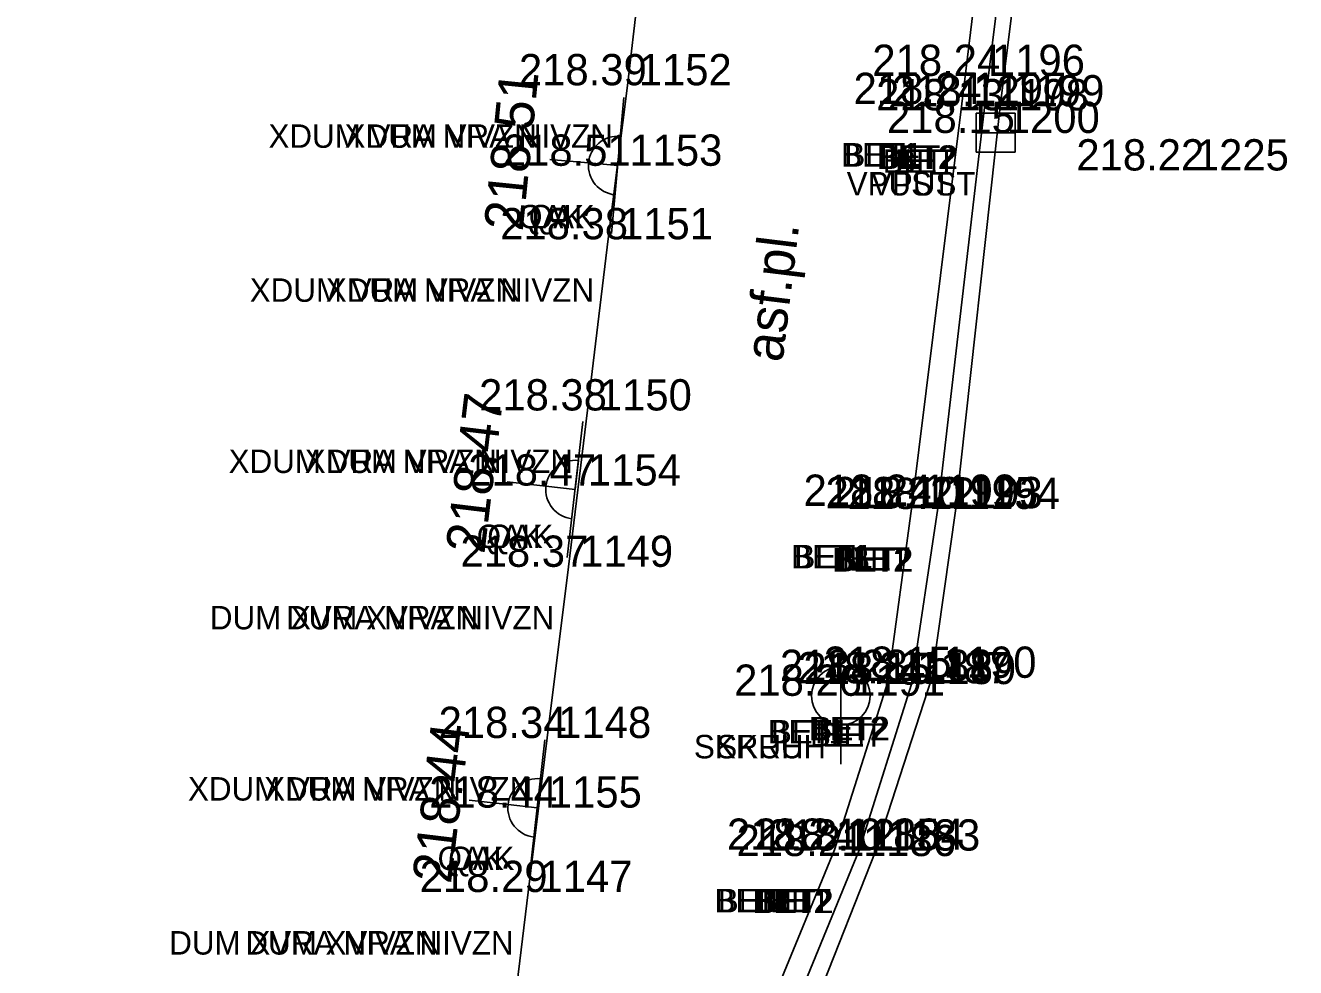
# Model space of a CAD drawing. Extents: x -471047 to -470889, y -1102859 to -1102000.
# Drawn here: x -470984.24 to -470967.99, y -1102458.3 to -1102446.24 of the extents above; entities that cross this region are included whole.
import ezdxf

# ---------------------------------------------------------------- set-up
doc = ezdxf.new("R2010")
doc.units = 0
for name, color, linetype in [('Vrstva 1', 7, 'Continuous'), ('Vrstva 10', 7, 'Continuous'), ('Vrstva 13', 7, 'Continuous'), ('Vrstva 22', 7, 'Continuous'), ('Vrstva 25', 7, 'Continuous'), ('Vrstva 28', 7, 'Continuous'), ('Vrstva 34', 7, 'Continuous'), ('Vrstva 35', 7, 'Continuous'), ('Vrstva 36', 7, 'Continuous'), ('Vrstva 38', 7, 'Continuous'), ('Vrstva 5', 7, 'Continuous'), ('Vrstva 7', 7, 'Continuous'), ('Vrstva 8', 7, 'Continuous')]:
    doc.layers.add(name, color=color, linetype=linetype)

msp = doc.modelspace()

# ---------------------------------------------------------------- linework, layer by layer
at = {"layer": 'Vrstva 1'}
for points in [[(-471040.344, -1102858.385), (-471031.676, -1102846.187), (-471026.357, -1102838.629), (-471023.212, -1102833.975), (-471019.21, -1102827.465), (-471016.861, -1102823.272), (-471013.099, -1102815.912), (-471010.824, -1102810.955), (-471007.329, -1102802.292), (-471005.34, -1102796.515), (-471002.842, -1102787.838), (-471001.3, -1102780.997), (-471000.19, -1102774.713), (-470999.247, -1102768.204), (-470998.794, -1102764.784), (-470997.199, -1102751.812), (-470994.899, -1102732.807), (-470992.551, -1102713.262), (-470990.326, -1102694.887), (-470988.122, -1102676.57), (-470985.812, -1102657.305), (-470983.537, -1102638.407), (-470981.386, -1102620.622), (-470979.843, -1102608.014), (-470976.377, -1102579.253), (-470972.945, -1102550.69), (-470970.475, -1102530.206), (-470967.905, -1102508.801), (-470965.053, -1102485.131), (-470962.734, -1102465.9), (-470960.173, -1102444.812), (-470957.795, -1102425.103), (-470954.965, -1102401.839), (-470953.834, -1102392.574), (-470952.33, -1102379.985), (-470950.744, -1102366.853), (-470948.978, -1102352.106), (-470947.037, -1102335.844), (-470944.949, -1102318.462), (-470944.013, -1102310.745), (-470942.39, -1102297.267), (-470939.519, -1102273.45), (-470937.593, -1102257.43), (-470936.064, -1102244.81), (-470934.114, -1102228.634), (-470931.621, -1102207.856), (-470929.536, -1102190.857), (-470926.572, -1102166.31), (-470924.91, -1102152.663), (-470923.413, -1102140.333), (-470921.923, -1102127.669), (-470921.155, -1102120.084), (-470920.446, -1102109.574), (-470919.912, -1102099.137), (-470919.63, -1102088.981), (-470919.523, -1102081.193), (-470919.563, -1102070.395), (-470919.714, -1102064.236), (-470920.134, -1102054.704), (-470920.462, -1102047.615), (-470920.599, -1102044.52), (-470920.743, -1102041.873), (-470921.125, -1102034.455), (-470921.774, -1102030.337), (-470922.418, -1102027.787), (-470923.734, -1102023.93), (-470924.872, -1102021.434), (-470926.752, -1102018.182), (-470927.953, -1102016.45), (-470929.616, -1102014.424), (-470932.252, -1102011.756), (-470935.111, -1102009.425), (-470938.391, -1102007.371), (-470942.651, -1102005.401)], [(-471041.328, -1102857.18), (-471032.144, -1102844.242), (-471027.583, -1102837.763), (-471024.388, -1102833.028), (-471020.451, -1102826.6), (-471018.089, -1102822.378), (-471014.542, -1102815.445), (-471012.233, -1102810.418), (-471009.247, -1102803.108), (-471006.795, -1102796.098), (-471004.315, -1102787.532), (-471002.782, -1102780.723), (-471001.674, -1102774.458), (-471000.75, -1102768.095), (-471000.28, -1102764.601), (-470998.692, -1102751.741), (-470996.378, -1102732.635), (-470994.028, -1102713.058), (-470991.808, -1102694.749), (-470989.616, -1102676.447), (-470987.284, -1102657.013), (-470985.031, -1102638.272), (-470982.87, -1102620.431), (-470981.334, -1102607.933), (-470977.881, -1102579.263), (-470974.429, -1102550.492), (-470971.964, -1102530.054), (-470969.391, -1102508.607), (-470966.54, -1102484.984), (-470964.231, -1102465.853), (-470961.679, -1102444.752), (-470959.304, -1102425.078), (-470956.455, -1102401.634), (-470955.339, -1102392.489), (-470953.812, -1102379.71), (-470952.249, -1102366.808), (-470950.479, -1102352.023), (-470948.536, -1102335.868), (-470946.426, -1102318.233), (-470945.493, -1102310.531), (-470943.864, -1102297.013), (-470940.984, -1102273.071), (-470939.078, -1102257.195), (-470937.559, -1102244.684), (-470935.592, -1102228.353), (-470933.101, -1102207.653), (-470931.011, -1102190.57), (-470928.046, -1102166.021), (-470926.409, -1102152.578), (-470924.898, -1102140.121), (-470923.427, -1102127.544), (-470922.647, -1102119.826), (-470921.919, -1102109.229), (-470921.42, -1102099.134), (-470921.127, -1102089.016), (-470921.023, -1102081.453), (-470921.061, -1102070.468), (-470921.209, -1102064.314), (-470921.666, -1102053.966), (-470922.156, -1102043.345), (-470922.299, -1102039.934), (-470922.637, -1102034.36), (-470923.091, -1102031.241), (-470923.847, -1102028.247), (-470925.083, -1102024.594), (-470926.222, -1102022.086), (-470928.04, -1102018.943), (-470929.138, -1102017.357), (-470930.929, -1102015.175), (-470933.062, -1102013.049), (-470936.379, -1102010.368), (-470939.169, -1102008.662), (-470942.899, -1102006.906), (-470945.661, -1102005.908)], [(-471043.557, -1102855.955), (-471035.129, -1102844.026), (-471029.872, -1102836.499), (-471026.577, -1102831.578), (-471022.675, -1102825.415), (-471020.123, -1102821.053), (-471016.667, -1102814.59), (-471014.208, -1102809.45), (-471011.177, -1102802.451), (-471008.55, -1102795.333), (-471006.082, -1102787.209), (-471004.464, -1102780.376), (-471003.265, -1102774.167), (-471002.327, -1102767.948), (-471001.636, -1102762.527), (-471000.297, -1102751.605), (-470997.959, -1102732.524), (-470995.602, -1102712.802), (-470993.412, -1102694.623), (-470991.21, -1102676.17), (-470988.891, -1102656.857), (-470986.625, -1102638.083), (-470984.455, -1102620.195), (-470982.936, -1102607.733), (-470979.497, -1102579.223), (-470976.023, -1102550.279), (-470973.554, -1102529.822), (-470970.991, -1102508.497), (-470968.146, -1102484.787), (-470965.835, -1102465.72), (-470963.284, -1102444.529), (-470960.91, -1102424.942), (-470958.043, -1102401.343), (-470956.946, -1102392.356), (-470955.396, -1102379.408), (-470953.851, -1102366.636), (-470952.049, -1102351.733), (-470950.124, -1102335.611), (-470948.034, -1102318.083), (-470947.094, -1102310.328), (-470945.421, -1102296.51), (-470942.58, -1102272.848), (-470940.675, -1102256.948), (-470939.176, -1102244.526), (-470937.187, -1102228.174), (-470934.708, -1102207.467), (-470932.621, -1102190.433), (-470929.634, -1102165.778), (-470928.004, -1102152.415), (-470926.45, -1102139.595), (-470925.003, -1102127.418), (-470924.249, -1102119.695), (-470923.515, -1102109.093), (-470923.018, -1102099.069), (-470922.711, -1102088.911), (-470922.643, -1102081.356), (-470922.797, -1102070.414), (-470923.018, -1102064.454), (-470923.52, -1102053.203), (-470923.823, -1102047.529), (-470924.123, -1102041.506), (-470924.462, -1102037.486), (-470924.934, -1102031.904), (-470925.664, -1102028.672), (-470926.771, -1102025.506), (-470927.959, -1102022.914), (-470929.674, -1102020.028), (-470930.76, -1102018.498), (-470932.447, -1102016.478), (-470935.215, -1102013.816), (-470937.644, -1102011.98), (-470940.381, -1102010.371), (-470943.968, -1102008.669), (-470947.145, -1102007.524), (-470950.874, -1102006.74)], [(-471044.756, -1102855.056), (-471036.376, -1102843.177), (-471031.167, -1102835.741), (-471027.859, -1102830.8), (-471023.934, -1102824.593), (-471021.43, -1102820.312), (-471018.011, -1102813.91), (-471015.536, -1102808.75), (-471012.578, -1102801.897), (-471009.95, -1102794.77), (-471007.561, -1102786.914), (-471005.936, -1102780.074), (-471004.727, -1102773.818), (-471003.828, -1102767.827), (-471003.121, -1102762.345), (-471001.787, -1102751.467), (-470999.446, -1102732.348), (-470997.073, -1102712.539), (-470994.902, -1102694.521), (-470992.696, -1102676.023), (-470990.376, -1102656.68), (-470988.131, -1102638.071), (-470985.947, -1102620.018), (-470984.417, -1102607.512), (-470980.993, -1102579.08), (-470977.514, -1102550.137), (-470975.048, -1102529.649), (-470972.488, -1102508.37), (-470969.618, -1102484.508), (-470967.34, -1102465.669), (-470964.767, -1102444.39), (-470962.402, -1102424.781), (-470959.534, -1102401.193), (-470958.432, -1102392.151), (-470956.883, -1102379.208), (-470955.335, -1102366.424), (-470953.535, -1102351.506), (-470951.606, -1102335.399), (-470949.519, -1102317.94), (-470948.575, -1102310.159), (-470946.889, -1102296.144), (-470944.056, -1102272.618), (-470942.139, -1102256.659), (-470940.657, -1102244.341), (-470938.638, -1102227.749), (-470936.19, -1102207.298), (-470934.102, -1102190.255), (-470931.124, -1102165.639), (-470929.492, -1102152.254), (-470927.915, -1102139.252), (-470926.46, -1102127.103), (-470925.74, -1102119.604), (-470925.012, -1102108.913), (-470924.523, -1102099.054), (-470924.217, -1102088.866), (-470924.148, -1102081.334), (-470924.301, -1102070.391), (-470924.518, -1102064.43), (-470924.97, -1102054.435), (-470925.588, -1102041.569), (-470925.963, -1102035.313), (-470926.405, -1102032.225), (-470927.078, -1102029.198), (-470928.123, -1102026.148), (-470929.318, -1102023.558), (-470930.84, -1102020.97), (-470931.868, -1102019.515), (-470933.443, -1102017.605), (-470936.26, -1102014.885), (-470938.429, -1102013.255), (-470941.213, -1102011.639), (-470944.847, -1102009.927), (-470947.723, -1102008.912), (-470951.444, -1102008.161), (-470954.511, -1102007.931), (-470957.895, -1102008.041)]]:
    msp.add_spline(points, degree=3, dxfattribs=at)
at = {"layer": 'Vrstva 10'}
for p, q in [((-470976.537, -1102447.015), (-470975.875, -1102441.337)), ((-470977.049, -1102451.166), (-470976.783, -1102448.976)), ((-470977.565, -1102455.356), (-470977.291, -1102453.17)), ((-470978.077, -1102459.537), (-470977.807, -1102457.33))]:
    msp.add_line(p, q, dxfattribs=at)
at = {"layer": 'Vrstva 13'}
for p, q in [((-470976.738, -1102448.908), (-470976.582, -1102447.166)), ((-470976.66, -1102448.037), (-470976.626, -1102447.664)), ((-470977.033, -1102448.003), (-470977.531, -1102447.959)), ((-470977.033, -1102448.003), (-470976.66, -1102448.037)), ((-470977.009, -1102448.006), (-470977.009, -1102448.006)), ((-470977.305, -1102453.051), (-470977.107, -1102451.313)), ((-470977.206, -1102452.182), (-470977.163, -1102451.809)), ((-470977.578, -1102452.14), (-470978.075, -1102452.083)), ((-470977.578, -1102452.14), (-470977.206, -1102452.182)), ((-470977.554, -1102452.142), (-470977.554, -1102452.142)), ((-470977.791, -1102457.123), (-470977.591, -1102455.385)), ((-470977.691, -1102456.254), (-470977.648, -1102455.881)), ((-470978.064, -1102456.211), (-470978.56, -1102456.154)), ((-470978.064, -1102456.211), (-470977.691, -1102456.254)), ((-470978.039, -1102456.214), (-470978.039, -1102456.214))]:
    msp.add_line(p, q, dxfattribs=at)
for centre, start, end in [((-470976.66, -1102448.037), 84.8548, 174.8548), ((-470976.66, -1102448.037), 174.8548, 264.8548), ((-470977.206, -1102452.182), 83.5126, 173.5126), ((-470977.206, -1102452.182), 173.5126, 263.5126), ((-470977.691, -1102456.254), 83.4375, 173.4375), ((-470977.691, -1102456.254), 173.4375, 263.4375)]:
    msp.add_arc(centre, 0.375, start, end, dxfattribs=at)
at = {"layer": 'Vrstva 25'}
for p, q in [((-470972.075, -1102447.367), (-470972.075, -1102447.867)), ((-470971.575, -1102447.367), (-470972.075, -1102447.367)), ((-470971.575, -1102447.867), (-470971.575, -1102447.367)), ((-470972.075, -1102447.617), (-470971.575, -1102447.617)), ((-470972.075, -1102447.867), (-470971.575, -1102447.867)), ((-470973.806, -1102455.195), (-470973.806, -1102454.445)), ((-470973.806, -1102455.195), (-470973.806, -1102455.695))]:
    msp.add_line(p, q, dxfattribs=at)
msp.add_circle((-470973.806, -1102454.82), 0.375, dxfattribs=at)
at = {"layer": 'Vrstva 28'}
for p, q in [((-470976.783, -1102448.976), (-470976.537, -1102447.015)), ((-470977.291, -1102453.17), (-470977.049, -1102451.166)), ((-470977.807, -1102457.33), (-470977.565, -1102455.356))]:
    msp.add_line(p, q, dxfattribs=at)
at = {"layer": 'Vrstva 34'}
for p, q in [((-470972.02, -1102446.89), (-470972.02, -1102446.89)), ((-470976.54, -1102447.01), (-470976.54, -1102447.01)), ((-470972.26, -1102447.25), (-470972.26, -1102447.25)), ((-470971.97, -1102447.33), (-470971.97, -1102447.33)), ((-470971.77, -1102447.28), (-470971.77, -1102447.28)), ((-470971.83, -1102447.62), (-470971.83, -1102447.62)), ((-470976.66, -1102448.04), (-470976.66, -1102448.04)), ((-470969.41, -1102448.1), (-470969.41, -1102448.1)), ((-470976.78, -1102448.98), (-470976.78, -1102448.98)), ((-470977.05, -1102451.17), (-470977.05, -1102451.17)), ((-470977.19, -1102452.13), (-470977.19, -1102452.13)), ((-470972.9, -1102452.39), (-470972.9, -1102452.39)), ((-470972.62, -1102452.42), (-470972.62, -1102452.42)), ((-470972.56, -1102452.42), (-470972.56, -1102452.42)), ((-470972.34, -1102452.43), (-470972.34, -1102452.43)), ((-470977.29, -1102453.17), (-470977.29, -1102453.17)), ((-470973.2, -1102454.63), (-470973.2, -1102454.63)), ((-470972.98, -1102454.66), (-470972.98, -1102454.66)), ((-470972.9, -1102454.67), (-470972.9, -1102454.67)), ((-470972.64, -1102454.59), (-470972.64, -1102454.59)), ((-470973.81, -1102454.82), (-470973.81, -1102454.82)), ((-470977.57, -1102455.36), (-470977.57, -1102455.36)), ((-470977.69, -1102456.25), (-470977.69, -1102456.25)), ((-470973.88, -1102456.79), (-470973.88, -1102456.79)), ((-470973.57, -1102456.79), (-470973.57, -1102456.79)), ((-470973.36, -1102456.8), (-470973.36, -1102456.8)), ((-470973.67, -1102456.87), (-470973.67, -1102456.87)), ((-470977.81, -1102457.33), (-470977.81, -1102457.33))]:
    msp.add_line(p, q, dxfattribs=at)
at = {"layer": 'Vrstva 5'}
for p, q in [((-470971.765, -1102447.282), (-470969.566, -1102429.53)), ((-470972.335, -1102452.425), (-470971.765, -1102447.282)), ((-470972.641, -1102454.59), (-470972.335, -1102452.425)), ((-470973.359, -1102456.799), (-470972.641, -1102454.59)), ((-470974.452, -1102459.569), (-470973.359, -1102456.799))]:
    msp.add_line(p, q, dxfattribs=at)
at = {"layer": 'Vrstva 7'}
for p, q in [((-470972.256, -1102447.249), (-470970.115, -1102429.388)), ((-470972.896, -1102452.394), (-470972.256, -1102447.249)), ((-470973.198, -1102454.63), (-470972.896, -1102452.394)), ((-470973.884, -1102456.792), (-470973.198, -1102454.63)), ((-470974.936, -1102459.332), (-470973.884, -1102456.792))]:
    msp.add_line(p, q, dxfattribs=at)
at = {"layer": 'Vrstva 8'}
for p, q in [((-470971.97, -1102447.332), (-470969.77, -1102429.442)), ((-470972.564, -1102452.421), (-470971.97, -1102447.332)), ((-470972.9, -1102454.669), (-470972.564, -1102452.421)), ((-470973.571, -1102456.793), (-470972.9, -1102454.669)), ((-470974.677, -1102459.49), (-470973.571, -1102456.793))]:
    msp.add_line(p, q, dxfattribs=at)

# ---------------------------------------------------------------- texts
at = {"layer": 'Vrstva 22'}
for s, rotation, p in [('218.51', 84.2702, (-470977.876, -1102448.886)), ('asf.pl.', 83.0293, (-470974.553, -1102450.564)), ('218.47', 83.1144, (-470978.367, -1102453.014)), ('218.44', 83.1144, (-470978.795, -1102457.234))]:
    msp.add_text(s, height=0.5, rotation=rotation, dxfattribs=at).set_placement(p)
at = {"layer": 'Vrstva 35'}
for s, p in [('XDUM VRA NIVZN', (-470981.129, -1102447.81)), ('XDUM VRA NIVZN', (-470980.155, -1102447.81)), ('BET1', (-470973.802, -1102448.05)), ('BET1', (-470973.76, -1102448.05)), ('BET2', (-470973.345, -1102448.08)), ('BET2', (-470973.311, -1102448.08)), ('BET', (-470973.27, -1102448.13)), ('BET', (-470973.109, -1102448.13)), ('VPUST', (-470973.73, -1102448.42)), ('VPUST', (-470973.419, -1102448.42)), ('QAK', (-470977.935, -1102448.84)), ('QAK', (-470977.799, -1102448.84)), ('XDUM VRA NIVZN', (-470981.369, -1102449.78)), ('XDUM VRA NIVZN', (-470980.395, -1102449.78)), ('XDUM VRA NIVZN', (-470981.639, -1102451.97)), ('XDUM VRA NIVZN', (-470980.665, -1102451.97)), ('QAK', (-470978.465, -1102452.93)), ('QAK', (-470978.329, -1102452.93)), ('BET1', (-470974.442, -1102453.19)), ('BET1', (-470974.4, -1102453.19)), ('BET2', (-470973.915, -1102453.23)), ('BET2', (-470973.881, -1102453.23)), ('BET', (-470973.86, -1102453.22)), ('BET', (-470973.699, -1102453.22)), ('DUM XVRA NIVZN', (-470981.879, -1102453.97)), ('DUM XVRA NIVZN', (-470980.905, -1102453.97)), ('BET1', (-470974.742, -1102455.43)), ('BET1', (-470974.7, -1102455.43)), ('BET2', (-470974.215, -1102455.39)), ('BET', (-470974.2, -1102455.47)), ('BET2', (-470974.181, -1102455.39)), ('BET', (-470974.039, -1102455.47)), ('SKRUH', (-470975.685, -1102455.62)), ('SKRUH', (-470975.399, -1102455.62)), ('XDUM VRA NIVZN', (-470982.159, -1102456.16)), ('XDUM VRA NIVZN', (-470981.185, -1102456.16)), ('QAK', (-470978.965, -1102457.05)), ('QAK', (-470978.829, -1102457.05)), ('BET1', (-470975.422, -1102457.59)), ('BET1', (-470975.38, -1102457.59)), ('BET2', (-470974.935, -1102457.6)), ('BET2', (-470974.901, -1102457.6)), ('BET', (-470974.87, -1102457.59)), ('BET', (-470974.709, -1102457.59)), ('DUM XVRA NIVZN', (-470982.399, -1102458.13)), ('DUM XVRA NIVZN', (-470981.425, -1102458.13))]:
    msp.add_text(s, height=0.3, dxfattribs=at).set_placement(p)
at = {"layer": 'Vrstva 36'}
for s, p in [(' 1196', (-470972.02, -1102446.89)), (' 1152', (-470976.54, -1102447.01)), (' 1197', (-470972.26, -1102447.25)), (' 1199', (-470971.77, -1102447.28)), (' 1198', (-470971.97, -1102447.33)), (' 1200', (-470971.83, -1102447.62)), (' 1153', (-470976.66, -1102448.04)), (' 1225', (-470969.41, -1102448.1)), (' 1151', (-470976.78, -1102448.98)), (' 1150', (-470977.05, -1102451.17)), (' 1154', (-470977.19, -1102452.13)), (' 1192', (-470972.9, -1102452.39)), (' 1195', (-470972.62, -1102452.42)), (' 1193', (-470972.56, -1102452.42)), (' 1194', (-470972.34, -1102452.43)), (' 1149', (-470977.29, -1102453.17)), (' 1188', (-470973.2, -1102454.63)), (' 1190', (-470972.64, -1102454.59)), (' 1187', (-470972.98, -1102454.66)), (' 1189', (-470972.9, -1102454.67)), (' 1191', (-470973.81, -1102454.82)), (' 1148', (-470977.57, -1102455.36)), (' 1155', (-470977.69, -1102456.25)), (' 1185', (-470973.88, -1102456.79)), (' 1186', (-470973.67, -1102456.87)), (' 1184', (-470973.57, -1102456.79)), (' 1183', (-470973.36, -1102456.8)), (' 1147', (-470977.81, -1102457.33))]:
    msp.add_text(s, height=0.4, dxfattribs=at).set_placement(p)
at = {"layer": 'Vrstva 38'}
for s, p in [('218.24 ', (-470973.402, -1102446.89)), ('218.39 ', (-470977.924, -1102447.01)), ('218.24 ', (-470973.642, -1102447.25)), ('218.12 ', (-470973.151, -1102447.28)), ('218.13 ', (-470973.353, -1102447.33)), ('218.15 ', (-470973.214, -1102447.62)), ('218.51 ', (-470978.13, -1102448.04)), ('218.22 ', (-470970.791, -1102448.1)), ('218.38 ', (-470978.164, -1102448.98)), ('218.38 ', (-470978.434, -1102451.17)), ('218.47 ', (-470978.573, -1102452.13)), ('218.24 ', (-470974.282, -1102452.39)), ('218.22 ', (-470974.001, -1102452.42)), ('218.10 ', (-470973.903, -1102452.42)), ('218.12 ', (-470973.721, -1102452.43)), ('218.37 ', (-470978.673, -1102453.17)), ('218.28 ', (-470974.584, -1102454.63)), ('218.15 ', (-470974.024, -1102454.59)), ('218.24 ', (-470974.362, -1102454.66)), ('218.15 ', (-470974.284, -1102454.67)), ('218.26 ', (-470975.17, -1102454.82)), ('218.34 ', (-470978.952, -1102455.36)), ('218.44 ', (-470979.072, -1102456.25)), ('218.24 ', (-470975.262, -1102456.79)), ('218.21 ', (-470975.14, -1102456.87)), ('218.10 ', (-470974.913, -1102456.79)), ('218.12 ', (-470974.741, -1102456.8)), ('218.29 ', (-470979.194, -1102457.33))]:
    msp.add_text(s, height=0.4, dxfattribs=at).set_placement(p)

doc.saveas('drawing.dxf')
